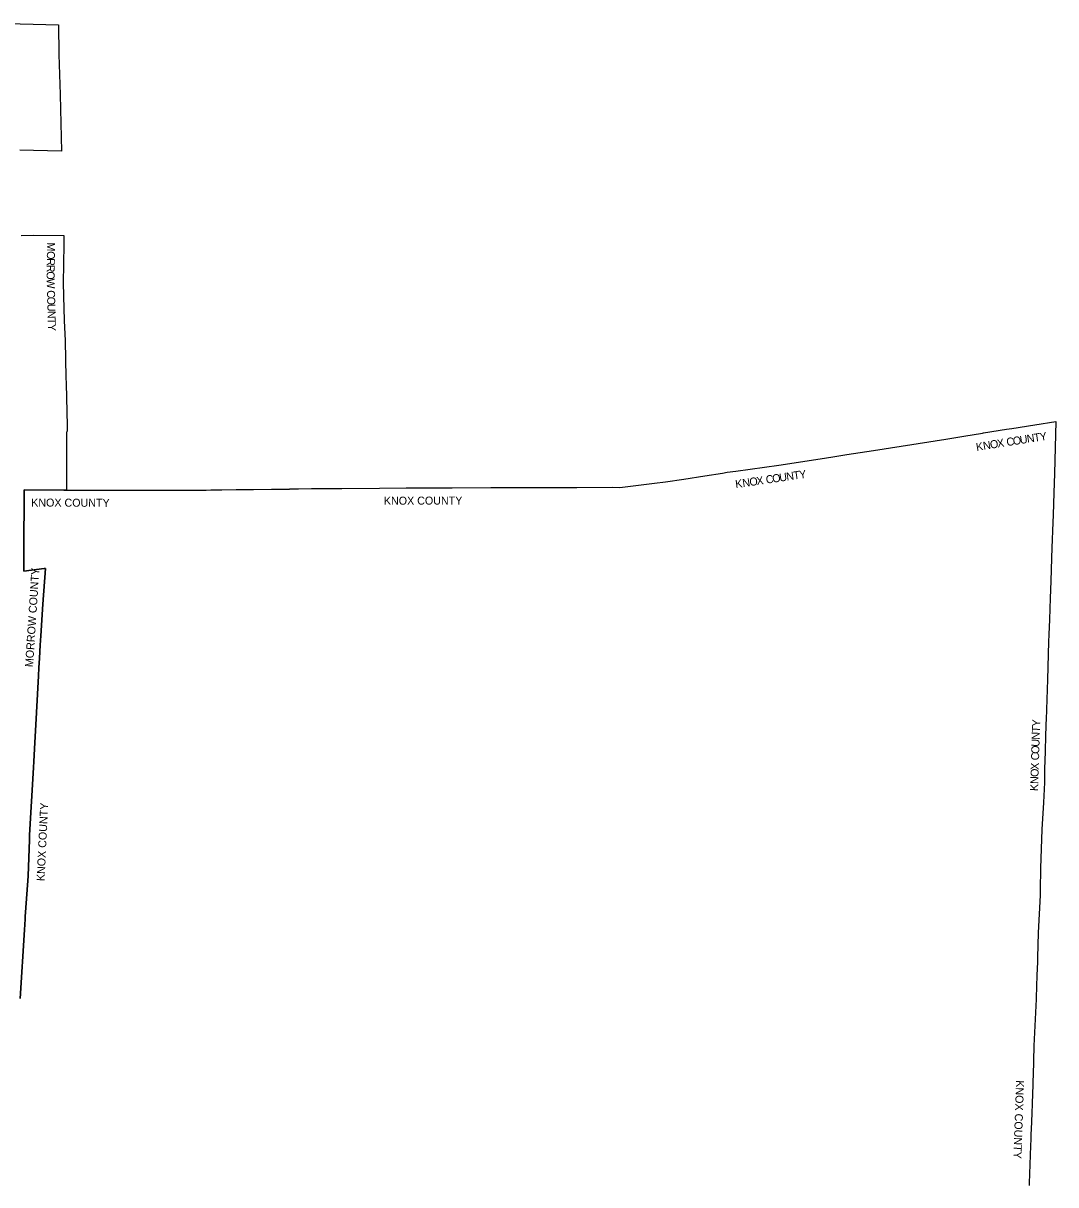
# Model space of a CAD drawing. Extents: x 1674899 to 2057726, y 653888 to 988278.
# Drawn here: x 1928708 to 2057726, y 842053 to 987155 of the extents above; entities that cross this region are included whole.
import ezdxf

# ---------------------------------------------------------------- set-up
doc = ezdxf.new("R2010")
doc.units = 0
doc.layers.add('GM_X_Adjacent_County', color=7, linetype='Continuous')
doc.layers.add('GM_X_Adjacent_County_Text', color=7, linetype='Continuous')

msp = doc.modelspace()

# ---------------------------------------------------------------- linework, layer by layer
at = {"layer": 'GM_X_Adjacent_County'}
for points in [[(1925127, 987155), (1933106, 986948), (1933172, 983252), (1933307, 978234), (1933364, 976428), (1933485, 971181), (1929986, 971246), (1928265, 971283)], [(1928467, 960653), (1930020, 960674), (1933801, 960656), (1933723, 955963), (1933713, 955812), (1933717, 954747), (1933720, 953054), (1933836, 950026), (1933939, 947488), (1934048, 942901), (1934067, 942157), (1934195, 936859), (1934202, 936590), (1934187, 936214), (1934165, 936177), (1934141, 936112), (1934134, 936040), (1934113, 935746), (1934115, 935394), (1934114, 935137), (1934107, 931513), (1934121, 929197), (1934122, 928828), (1933789, 928831), (1928810, 928882), (1928810, 928443), (1928806, 926508), (1928802, 923466), (1928787, 918701), (1931337, 919032), (1931473, 919044), (1931168, 914595), (1930891, 910644), (1930824, 909461), (1930733, 907844), (1930665, 906634), (1930611, 905616), (1930247, 898751), (1930144, 897297), (1930019, 894924), (1929994, 894165), (1929509, 885709), (1929483, 885147), (1929313, 880637), (1929312, 880613), (1928987, 876105), (1928954, 875572), (1928932, 875213), (1928849, 873883), (1928341, 865325)], [(1928341, 865325), (1928849, 873883), (1928932, 875213), (1928954, 875572), (1928987, 876105), (1929312, 880613), (1929313, 880637), (1929483, 885147), (1929509, 885709), (1929994, 894165), (1930019, 894924), (1930144, 897297), (1930247, 898751), (1930611, 905616), (1930665, 906634), (1930733, 907844), (1930824, 909461), (1930891, 910644), (1931168, 914595), (1931473, 919044), (1931337, 919032), (1928787, 918701), (1928802, 923466), (1928806, 926508), (1928810, 928443), (1928810, 928882), (1933789, 928831), (1934122, 928828), (1934664, 928840), (1941462, 928831), (1944689, 928838), (1949281, 928821), (1949992, 928829), (1951568, 928828), (1952146, 928858), (1953542, 928878), (1955313, 928900), (1957476, 928914), (1959742, 928940), (1961813, 928963), (1961959, 928969), (1961985, 928970), (1963113, 928985), (1964738, 929020), (1965966, 929036), (1967022, 929051), (1968500, 929038), (1973229, 929089), (1976549, 929096), (1977276, 929098), (1981906, 929112), (1982296, 929113), (1987142, 929172), (1990714, 929138), (1992067, 929138), (1994873, 929158), (1997884, 929140), (2002301, 929187), (2003242, 929141), (2007573, 929691), (2008943, 929865), (2011234, 930213), (2013857, 930619), (2016073, 930958), (2016684, 931060), (2017738, 931179), (2023140, 931954), (2028816, 932841), (2030108, 933014), (2031111, 933198), (2031637, 933277), (2034945, 933785), (2038391, 934329), (2043971, 935214), (2046246, 935556), (2048556, 935944), (2048711, 935978), (2051568, 936428), (2052246, 936535), (2055097, 936994), (2057726, 937388), (2057555, 930907), (2057486, 928485), (2057388, 925732), (2057353, 924798), (2057237, 921621), (2057194, 920316), (2057099, 917440), (2057032, 915337), (2056947, 912673), (2056846, 910775), (2056822, 909880), (2056672, 905166), (2056513, 900187), (2056508, 900013), (2056501, 899793), (2056492, 899507), (2056355, 894845), (2056323, 894207), (2056314, 893810), (2056304, 892311), (2056178, 889804), (2056003, 886437), (2055830, 881597), (2055758, 878857), (2055764, 878233), (2055530, 873508), (2055459, 870464), (2055437, 869889), (2055435, 869840), (2055376, 868233), (2055265, 865388), (2055262, 865248), (2054986, 859394), (2054896, 855720), (2054860, 855058), (2054857, 854576), (2054761, 852209), (2054715, 850940), (2054639, 848991), (2054625, 848376), (2054594, 847730), (2054575, 846927), (2054411, 842272), (2054399, 841942)]]:
    msp.add_lwpolyline(points, dxfattribs=at)

# ---------------------------------------------------------------- texts
at = {"layer": 'GM_X_Adjacent_County_Text'}
for s, rotation, p in [('M', 269.0655, (1931694, 959777)), ('R', 269.03708, (1931662, 957806)), ('O', 269.05827, (1931676, 958691)), ('R', 268.94962, (1931648, 956993)), ('O', 270.20879, (1931633, 956155)), ('W', 271.42186, (1931636, 955247)), ('C', 271.4779, (1931673, 953790)), ('O', 271.48122, (1931694, 952977)), ('U', 271.48182, (1931717, 952093)), ('N', 271.48182, (1931739, 951208)), ('T', 271.48127, (1931762, 950324)), ('Y', 271.48287, (1931782, 949577)), ('T', 8.94765, (2055059, 934861)), ('Y', 8.9464, (2055798, 934977)), ('K', 9.45553, (2047842, 933705)), ('N', 9.64945, (2048718, 933850)), ('O', 9.00146, (2049587, 933998)), ('X', 8.95533, (2050460, 934137)), ('C', 8.9515, (2051634, 934321)), ('O', 8.94425, (2052438, 934448)), ('U', 8.94792, (2053312, 934586)), ('N', 8.9464, (2054185, 934723)), ('K', 7.07188, (2017739, 929089)), ('N', 8.28683, (2018639, 929201)), ('O', 8.40884, (2019517, 929329)), ('X', 8.44123, (2020392, 929458)), ('C', 8.4422, (2021568, 929633)), ('O', 8.44409, (2022373, 929752)), ('U', 8.44258, (2023248, 929882)), ('N', 8.44258, (2024123, 930012)), ('T', 8.44265, (2024997, 930142)), ('Y', 8.44258, (2025737, 930251)), ('KNOX COUNTY', 359.74688, (1929702, 926781)), ('KNOX COUNTY', 0.14338, (1973773, 927006)), ('MORROW COUNTY', 86.28759, (1929931, 906690)), ('Y', 87.22822, (2055754, 899272)), ('N', 88.31211, (2055706, 897645)), ('T', 88.26662, (2055732, 898529)), ('O', 88.31211, (2055654, 895877)), ('U', 88.31211, (2055680, 896761)), ('C', 88.31247, (2055630, 895064)), ('O', 88.31211, (2055569, 892992)), ('X', 88.31211, (2055595, 893876)), ('N', 88.31211, (2055542, 892108)), ('K', 88.31211, (2055516, 891224)), ('KNOX COUNTY', 87.27243, (1931370, 879966)), ('KNOX COUNTY', 268.03397, (2052766, 855120))]:
    msp.add_text(s, height=1000, rotation=rotation, dxfattribs=at).set_placement(p)

doc.saveas('drawing.dxf')
